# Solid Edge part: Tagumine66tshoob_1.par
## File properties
Author: KULL
Template: Iso Metric Part.par
Last saved by: KULL
Revision: 33
Application: Solid Edge
Density: 2712,000 kg/m^3
Accuracy: 0,990
Material: Aluminum, 1060
Face Style: Aluminum
Fill Style: ANSI38(Aluminum)
Virtual Style: Polished aluminum
Categorization: Metals\Aluminium Alloys
LibraryName: Materials
Coef. of Thermal Exp: 2.3e-05
Thermal Conductivity: 221.0
Specific Heat: 920.0
Modulus of Elasticity: 68947570000.0
Poisson's Ratio: 0.33
Yield Stress: 27579028.0
Ultimate Stress: 68947570.0
Elongation: 0.0
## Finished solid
Body 1: sheet body, 2 faces, 31 edges, 31 vertices.
  Faces by surface: plane 2
  Edges by curve: intersection 17, circle 7, line 7
Body 2: sheet body, 2 faces, 31 edges, 31 vertices.
  Faces by surface: plane 2
  Edges by curve: intersection 17, circle 7, line 7
Body 3: sheet body, 2 faces, 31 edges, 31 vertices.
  Faces by surface: plane 2
  Edges by curve: intersection 17, circle 7, line 7
Body 4: sheet body, 1 face, 38 edges, 38 vertices.
  Faces by surface: offset 1
  Edges by curve: curve on surface 38
Body 5: sheet body, 1 face, 42 edges, 42 vertices.
  Faces by surface: offset 1
  Edges by curve: curve on surface 42
Body 6: sheet body, 5 faces, 16 edges, 12 vertices.
  Faces by surface: plane 3, cylinder 2
  Edges by curve: line 12, circle 4
Body 7: sheet body, 5 faces, 16 edges, 12 vertices.
  Faces by surface: plane 3, cylinder 2
  Edges by curve: line 12, circle 4
Body 8: solid body, 578 faces, 1234 edges, 670 vertices.
  Faces by surface: blend 365, spline 59, sphere 55, plane 30, cylinder 28, torus 27, offset 13, cone 1
  Edges by curve: intersection 729, circle 467, line 37, curve on surface 1
Body 9: sheet body, 5 faces, 16 edges, 12 vertices.
  Faces by surface: plane 3, cylinder 2
  Edges by curve: line 12, circle 4
Body 10: sheet body, 2 faces, 31 edges, 31 vertices.
  Faces by surface: plane 2
  Edges by curve: intersection 17, circle 7, line 7
Body 11: sheet body, 2 faces, 31 edges, 31 vertices.
  Faces by surface: plane 2
  Edges by curve: intersection 17, circle 7, line 7
Body 12: sheet body, 2 faces, 31 edges, 31 vertices.
  Faces by surface: plane 2
  Edges by curve: intersection 17, circle 7, line 7
Bounding box of the edges (mm; curved faces can reach further): 179.671 x 75.000 x 21.811, from (-432.2955, 40, -6) to (-252.6245, 115, 15.811).
Cylindrical faces by radius (mm): R0.4 x6, R1.5 x1, R2.5 x2, R2.9732 x1, R5 x4, R7 x2, R7.9504 x1, R8.5905 x1, R9.9504 x1, R10.5905 x1, R10.611 x1, R12.611 x1, R18 x2, R20 x4, R21.7545 x1, R22 x4, R23.7545 x1
Conical faces (half-angle, radius in mm at the cone's reference point): 40.1033 deg R3.865 x1
Toroidal faces (ring radius, tube radius in mm): R2.5732 r0.4 x2, R3.9041 r0.4 x1, R4.4 r0.6 x8, R4.5371 r1.485 x1, R4.996 r0.6 x1, R5.3 r0.3 x8, R5.7982 r0.6 x1, R6 r1 x4, R6.9857 r1 x1
Spherical faces by radius (mm): R0.1 x53, R4 x1, R6 x1
Planar faces by outward normal: +x 9, -x 9, oblique 12
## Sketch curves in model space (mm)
line (-368.96, 101.2879, -3.6288) -> (-368.96, 87.844, -4.285)
line (0, 45, 10.811) -> (0, 41.2212, 10.811)
line (0, 45, 10.811) -> (0, 124.4191, 10.811)
line (-312.46, 45, 10.811) -> (-318.46, 45, 10.811)
line (-301.46, 45, 10.811) -> (-306.46, 45, 10.811)
line (-383.46, 45.533, 10.7209) -> (-378.46, 45.533, 10.7209)
line (-383.46, 45, 10.811) -> (-378.46, 45, 10.811)
line (-322.46, 45, 10.811) -> (-322.46, 53.5656, 9.3641)
line (-342.46, 45, 10.811) -> (-322.46, 45, 10.811)
line (-342.46, 45, 10.811) -> (-362.46, 45, 10.811)
line (-376.5748, 45.533, 10.7209) -> (-367.46, 45.533, 10.7209)
line (-376.5748, 45.533, 10.7209) -> (-362.46, 45.533, 10.7209)
line (-342.46, 36.201, 12.2973) -> (-301.46, 36.201, 12.2973)
line (-342.46, 36.201, 12.2973) -> (-383.46, 36.201, 12.2973)
line (-298.2547, 45, 10.811) -> (-386.6653, 45, 10.811)
line (-342.46, 109, 8.9348) -> (-342.46, 109, -10.66)
line (-342.46, 0, 0) -> (-342.46, 109, 0)
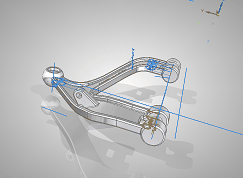
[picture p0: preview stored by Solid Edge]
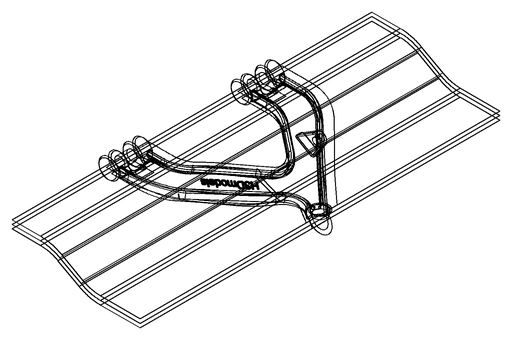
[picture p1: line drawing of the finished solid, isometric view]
